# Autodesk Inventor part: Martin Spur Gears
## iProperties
Author: BBM
Shininess: 64.0
Angle Display Precision: 2
Document Length Units: 11272
Document Angle Units: 11286
Document Time Units: 11279
Document Mass Units: 11290
Document Length Units Precision: 3
Document Angle Units Precision: 2
Compacted: True
PropertySet Name: _Private Model Information
Created: 2002-03
Part Number: Martin Spur Gears
Material: Steel, High Strength Low Alloy
Document SubType Name: Modeling
Designer: BBM
Control State: 0
Master: False
Checked Out: False
PropertySet Name: Design Tracking Control
Density: 0.0
Volumn: 0.0
Area: 0.0
PropertySet Name: Model Information
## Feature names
1. Revolution1
2. Extrusion1
3. Circular Pattern1
4. Extrusion2
5. Fillet1
